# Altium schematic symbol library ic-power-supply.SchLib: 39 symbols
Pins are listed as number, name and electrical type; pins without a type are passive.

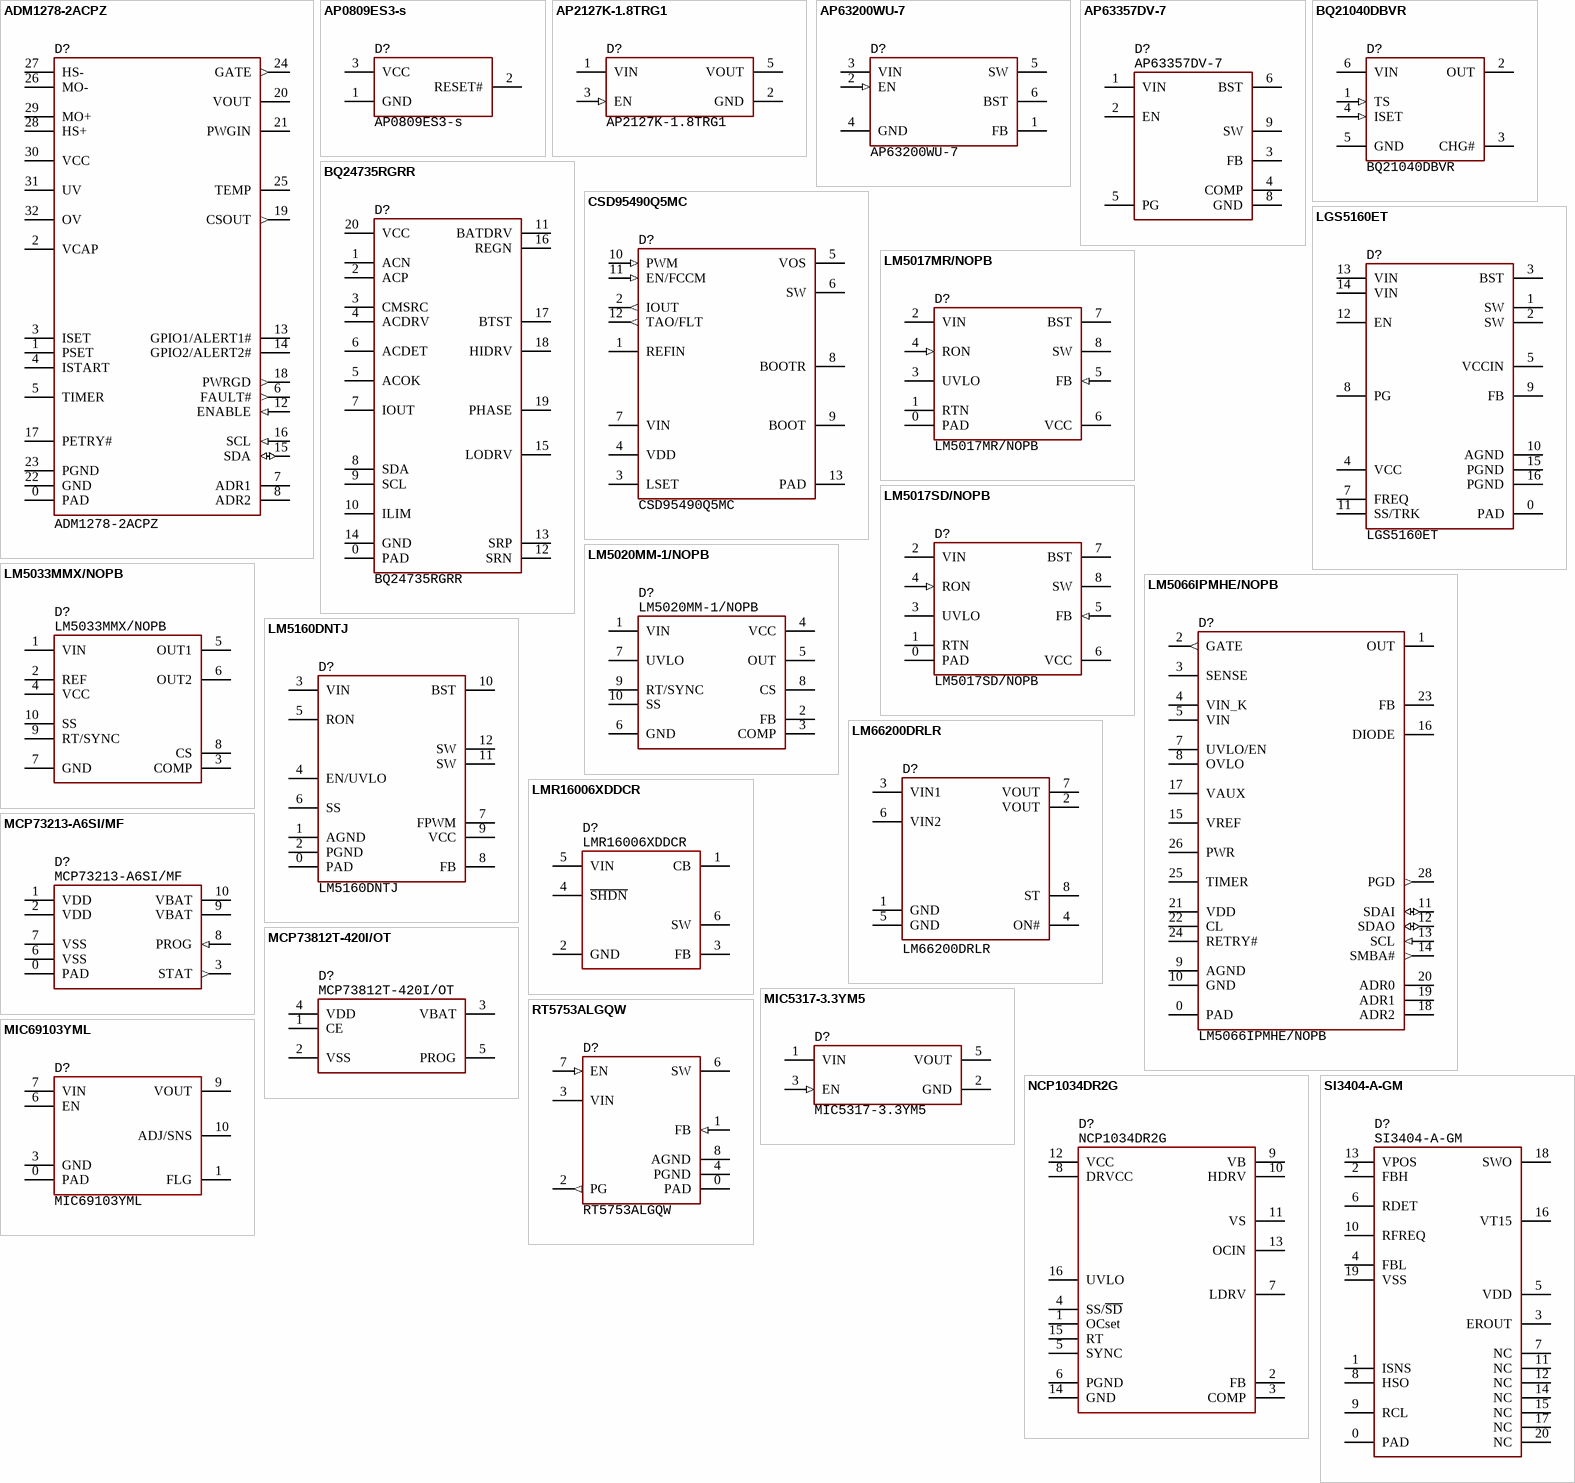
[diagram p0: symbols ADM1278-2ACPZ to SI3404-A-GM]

## ADM1278-2ACPZ
designator D?
Hot Swap Controller, supply 4.5...20V, QFN-32, -40...+85°C; Manufacturer: Analog Devices
footprint 32-QFN (5x5, pitch 0.5) (5x5 mm, pitch 0.5 mm, power pad)
pins: 0 PAD, 1 PSET, 2 VCAP, 3 ISET, 4 ISTART, 5 TIMER, 6 FAULT# (out), 7 ADR1, 8 ADR2, 12 ENABLE (in), 13 GPIO1/ALERT1#, 14 GPIO2/ALERT2#, 15 SDA (io), 16 SCL (in), 17 PETRY#, 18 PWRGD (out), 19 CSOUT (out), 20 VOUT, 21 PWGIN, 22 GND, 23 PGND, 24 GATE (out), 25 TEMP, 26 MO-, 27 HS-, 28 HS+, 29 MO+, 30 VCC, 31 UV, 32 OV

## AP0809ES3-s
designator D?
POR supervisor, 2.97V, SOT-23, -40...+105°C; Manufacturer: Chipown
footprint SOT23
pins: 1 GND, 2 RESET#, 3 VCC

## AP2127K-1.8TRG1
designator D?
LDO, output 1.8V, input 2.5...6V, 300 mA, -40...+85°C; Manufacture: Diodes
footprint SOT23-5 (pitch 0.95 mm)
pins: 1 VIN, 2 GND, 3 EN (in), 5 VOUT

## AP63200WU-7
designator D?  PartNumber: AP63200WU-7
Buck sync, 2A, 500kHz, input 3.8...32V, SOT23-6, -40...+85°C; Manufacturer: Diodes
footprint SOT23-6 (pitch 0.95 mm)
pins: 1 FB, 2 EN (in), 3 VIN, 4 GND, 5 SW, 6 BST

## AP63357DV-7
designator D?  PartNumber: AP63357DV-7
Buck sync, 3.5A, 450kHz, input 3.8...32V, DFN3020, -40...+85°C; Manufacturer: Diodes
footprint IC: AP63357DV-7
pins: 1 VIN, 2 EN, 3 FB, 4 COMP, 5 PG, 6 BST, 8 GND, 9 SW

## BQ21040DBVR
designator D?
Charger 1S, 800 mA, supply 3.5...28V, SOT23-6, 0...+125°C; Manufacture: Texas Instruments
footprint SOT23-6 (pitch 0.95 mm)
pins: 1 TS (in), 2 OUT, 3 CHG#, 4 ISET (in), 5 GND, 6 VIN

## BQ24735RGRR
designator D?
Charger 1...4S, 8A, supply 4.5...24V, QFN-20, -40...+85°C; Manufacture: Texas Instruments
footprint 20-QFN (3.5x3.5) (20-VQFN, pitch 0.5 mm)
pins: 0 PAD, 1 ACN, 2 ACP, 3 CMSRC, 4 ACDRV, 5 ACOK, 6 ACDET, 7 IOUT, 8 SDA, 9 SCL, 10 ILIM, 11 BATDRV, 12 SRN, 13 SRP, 14 GND, 15 LODRV, 16 REGN, 17 BTST, 18 HIDRV, 19 PHASE, 20 VCC

## CSD95490Q5MC
designator D?
DrMOS, input 3...16V, supply 4.75...5.25V, 75A, up to 1.25 MHz, QFN 5x6, -40...+125°C; Manufacturer: Texas Instruments
footprint IC: CSD95490Q5MC
pins: 1 REFIN, 2 IOUT (out), 3 LSET, 4 VDD, 5 VOS, 6 SW, 7 VIN, 8 BOOTR, 9 BOOT, 10 PWM (in), 11 EN/FCCM (in), 12 TAO/FLT (out), 13 PAD

## LGS5160ET
designator D?
Buck sync, 2.5A, up to 2 MHz, supply 4...60V, TSSOP-16, -40...+125°C; Manufacturer: Legend-Si
footprint 16-SSOP (PAD) (pitch 0.635 mm)
pins: 0 PAD, 1 SW, 2 SW, 3 BST, 4 VCC, 5 VCCIN, 7 FREQ, 8 PG, 9 FB, 10 AGND, 11 SS/TRK, 12 EN, 13 VIN, 14 VIN, 15 PGND, 16 PGND

## LM5017MR/NOPB
designator D?
Buck sync, 0.6A, 1MHz, supply 7.5...100V, SOIC-8, -40...+125°C; Manufacturer: Texas Instruments
footprint 8-SOIC-PAD (pitch 1.27 mm, power pad)
pins: 0 PAD, 1 RTN, 2 VIN, 3 UVLO, 4 RON (in), 5 FB (in), 6 VCC, 7 BST, 8 SW

## LM5017SD/NOPB
designator D?
Buck sync, 0.6A, 1MHz, supply 7.5...100V, WSON-8, -40...+125°C; Manufacturer: Texas Instruments
footprint 8-WSON (4x4) (4x4 mm, pitch 0.8 mm, power pad)
pins: 0 PAD, 1 RTN, 2 VIN, 3 UVLO, 4 RON (in), 5 FB (in), 6 VCC, 7 BST, 8 SW

## LM5020MM-1/NOPB
designator D?
PWM controller, 100...1000 kHz, supply 13...100V, MSOP-10, -40...+125°C; Manufacture: Texas Instruments
footprint 10-MSOP (3x3 mm, pitch 0.5 mm)
pins: 1 VIN, 2 FB, 3 COMP, 4 VCC, 5 OUT, 6 GND, 7 UVLO, 8 CS, 9 RT/SYNC, 10 SS

## LM5033MMX/NOPB
designator D?
PWM controller, PP, 100...1000 kHz, supply 15...100V, MSOP-10, -40...+125°C; Manufacture: Texas Instruments
footprint 10-MSOP (3x3 mm, pitch 0.5 mm)
pins: 1 VIN, 2 REF, 3 COMP, 4 VCC, 5 OUT1, 6 OUT2, 7 GND, 8 CS, 9 RT/SYNC, 10 SS

## LM5066IPMHE/NOPB
designator D?
Hot Swap Controller, supply 10...80V, HTSSOP-28, -40...+125°C; Manufacturer: Texas Instruments
footprint 28-TSSOP-PAD (pitch 0.65 mm)
pins: 0 PAD, 1 OUT, 2 GATE (out), 3 SENSE, 4 VIN_K, 5 VIN, 7 UVLO/EN, 8 OVLO, 9 AGND, 10 GND, 11 SDAI (io), 12 SDAO (io), 13 SCL (in), 14 SMBA# (out), 15 VREF, 16 DIODE, 17 VAUX, 18 ADR2, 19 ADR1, 20 ADR0, 21 VDD, 22 CL, 23 FB, 24 RETRY#, 25 TIMER, 26 PWR, 28 PGD (out)

## LM5160DNTJ
designator D?
Buck sync, 2A, up to 1MHz, input 4.5...65V, output 2...60V, WSON-12, -40...+85°C; Manufacturer: Texas Instruments
footprint 12-WSON (4x4x0.5)
pins: 0 PAD, 1 AGND, 2 PGND, 3 VIN, 4 EN/UVLO, 5 RON, 6 SS, 7 FPWM, 8 FB, 9 VCC, 10 BST, 11 SW, 12 SW

## LM66200DRLR
designator D?
Dual OR controller, 2.5A, supply 1.6...5.5V, SOT-5X3, -40...+125°C; Manufacture: Texas Instruments
footprint SOT-583 (pitch 0.95 mm)
pins: 1 GND, 2 VOUT, 3 VIN1, 4 ON#, 5 GND, 6 VIN2, 7 VOUT, 8 ST

## LMR16006XDDCR
designator D?
Buck sync, 0.6A, 700kHz, supply 4...60V, SOT23-6, -40...+125°C; Manufacturer: Texas Instruments
footprint SOT23-6 (pitch 0.95 mm)
pins: 1 CB, 2 GND, 3 FB, 4 ~{SHDN}, 5 VIN, 6 SW

## MCP73213-A6SI/MF
designator D?
Charger 2S, 1.1A, supply 4.2...13V, DFN-10, -40...+85°C; Manufacture: Microchip
footprint 10-DFN (3x3) (3x3 mm, pitch 0.5 mm, power pad)
pins: 0 PAD, 1 VDD, 2 VDD, 3 STAT (out), 6 VSS, 7 VSS, 8 PROG (in), 9 VBAT, 10 VBAT

## MCP73812T-420I/OT
designator D?
Charger 1S, 500 mA, supply 3.75...6V, SOT23-5, -40...+85°C; Manufacture: Microchip
footprint SOT23-5 (pitch 0.95 mm)
pins: 1 CE, 2 VSS, 3 VBAT, 4 VDD, 5 PROG

## MIC5317-3.3YM5
designator D?
LDO, output 3.3V, input 2.5...6V, 150 mA, -40...+85°C; Manufacture: Diodes
footprint SOT23-5 (pitch 0.95 mm)
pins: 1 VIN, 2 GND, 3 EN (in), 5 VOUT

## MIC69103YML
designator D?
LDO, 1A, dropout 0.5V, supply 1.65...5.5V, DFN-8, -40...+125°C; Manufacturer: Microchip
footprint 10-DFN (3x3) (3x3 mm, pitch 0.5 mm, power pad)
pins: 0 PAD, 1 FLG, 3 GND, 6 EN, 7 VIN, 9 VOUT, 10 ADJ/SNS

## NCP1034DR2G
designator D?
Buck controller, 2A, 25...500kHz, supply 10 ...100V, WSON-8, -40...+125°C; Manufacturer: ON Semiconductor
footprint 16-SO (pitch 1.27 mm)
pins: 1 OCset, 2 FB, 3 COMP, 4 SS/~{SD}, 5 SYNC, 6 PGND, 7 LDRV, 8 DRVCC, 9 VB, 10 HDRV, 11 VS, 12 VCC, 13 OCIN, 14 GND, 15 RT, 16 UVLO

## RT5753ALGQW
designator D?
Buck sync, 3A, input 2.5...5.5V, 1.2 MHz, output 0.6V, WDFN-8L, -40...+125°C; Manufacturer: Richtek
footprint 8-DFN (2x2, 0.5 mm)
pins: 0 PAD, 1 FB (in), 2 PG (out), 3 VIN, 4 PGND, 6 SW, 7 EN (in), 8 AGND

## SI3404-A-GM
designator D?
PoE, supply 1.5...57V, 600 mA, 470 kHz, QFN-20, -40...+125°C; Manufacture: Skyworks
footprint 20-QFN (4x4, pitch 0.5) (4x4 mm, pitch 0.5 mm, power pad)
pins: 0 PAD, 1 ISNS, 2 FBH, 3 EROUT, 4 FBL, 5 VDD, 6 RDET, 7 NC, 8 HSO, 9 RCL, 10 RFREQ, 11 NC, 12 NC, 13 VPOS, 14 NC, 15 NC, 16 VT15, 17 NC, 18 SWO, 19 VSS, 20 NC

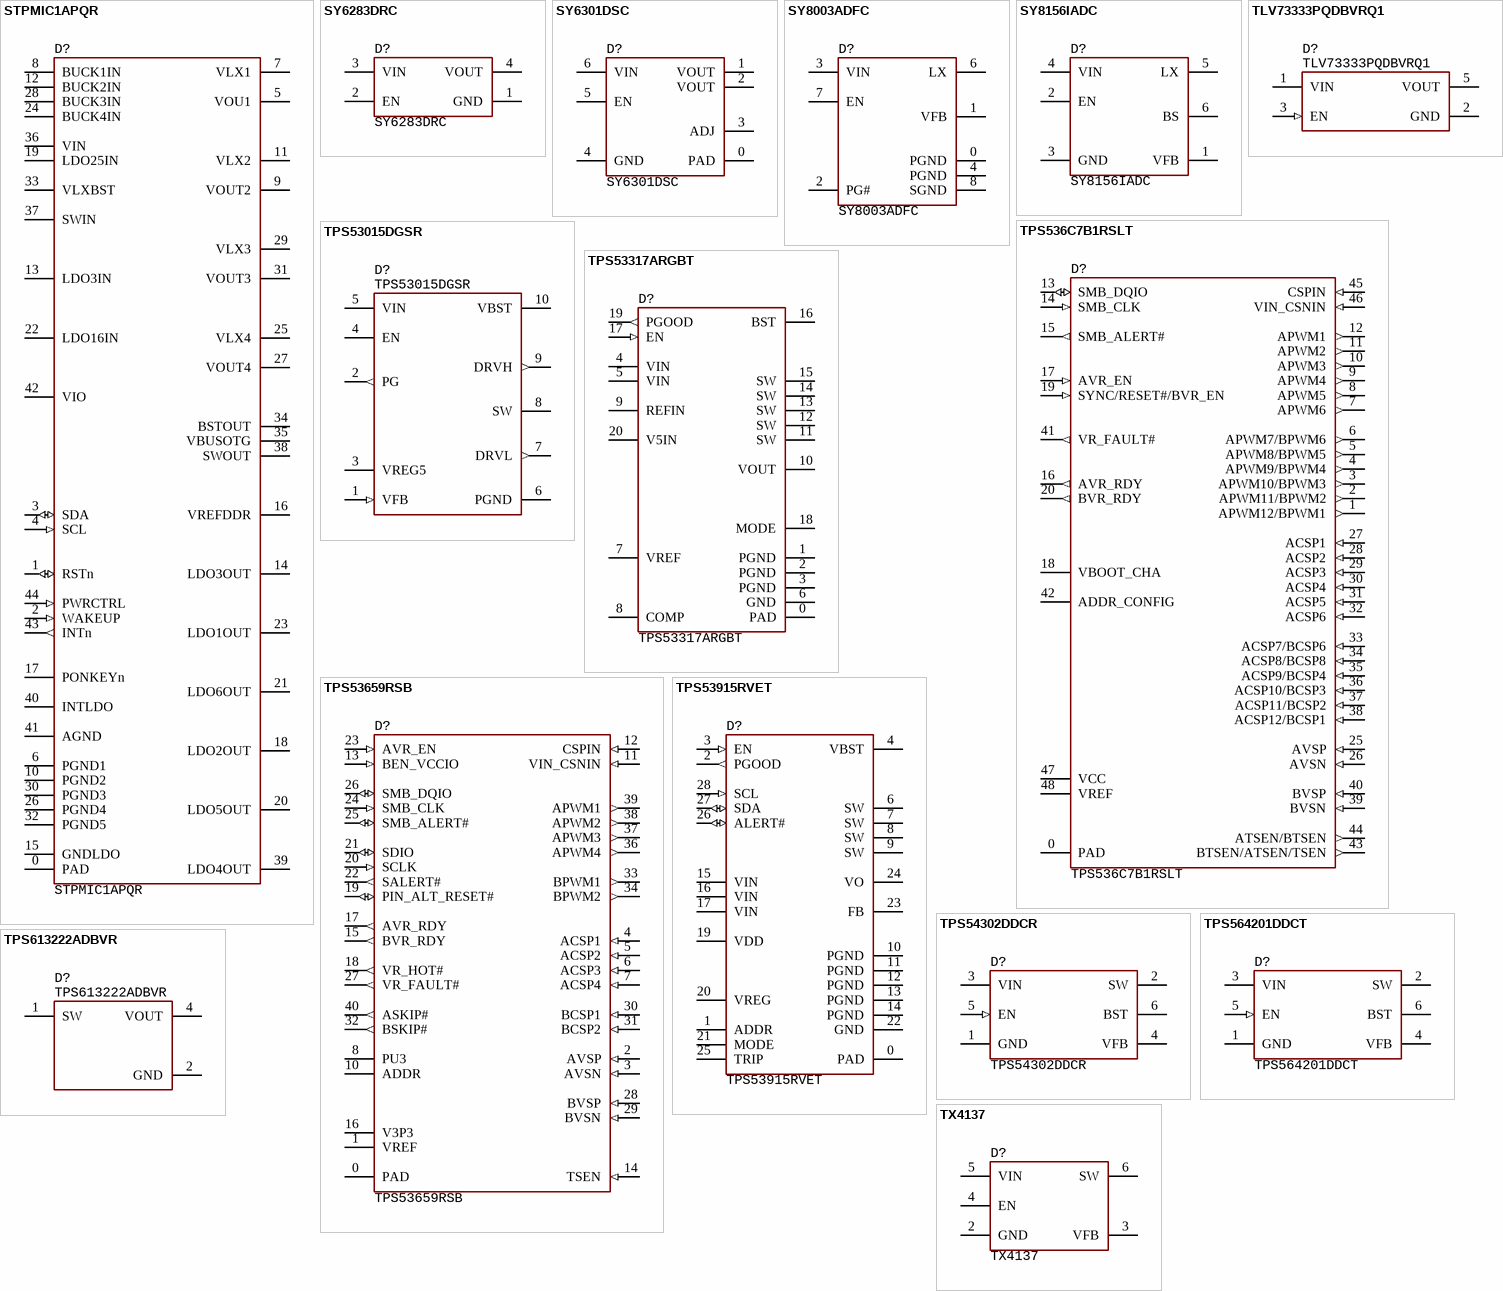
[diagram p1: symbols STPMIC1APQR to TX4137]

## STPMIC1APQR
designator D?  PartNumber: STPMIC1APQR
PMIC, 4 DC/DC + 7 LDO, input 2.8...5.5V, 44-WFQFN, -40...+105°C; Manufacturer: STMicroelectronics
footprint 44-WFQFN (5x6, pitch 0.4) (44-QFN, 5x6mm, pitch 0,40mm)
pins: 0 PAD, 1 RSTn (io), 2 WAKEUP (in), 3 SDA (io), 4 SCL (in), 5 VOU1, 6 PGND1, 7 VLX1, 8 BUCK1IN, 9 VOUT2, 10 PGND2, 11 VLX2, 12 BUCK2IN, 13 LDO3IN, 14 LDO3OUT, 15 GNDLDO, 16 VREFDDR, 17 PONKEYn, 18 LDO2OUT, 19 LDO25IN, 20 LDO5OUT, 21 LDO6OUT, 22 LDO16IN, 23 LDO1OUT, 24 BUCK4IN, 25 VLX4, 26 PGND4, 27 VOUT4, 28 BUCK3IN, 29 VLX3, 30 PGND3, 31 VOUT3, 32 PGND5, 33 VLXBST, 34 BSTOUT, 35 VBUSOTG, 36 VIN, 37 SWIN, 38 SWOUT, 39 LDO4OUT, 40 INTLDO, 41 AGND, 42 VIO, 43 INTn (out), 44 PWRCTRL (in)

## SY6283DRC
designator D?
Switches, 2.5...5.5V, 3A, DFN-4, -40...+85°C; Manufacturer: Silergy
footprint 4-DFN (1.2x1.6, 0.5 mm)
pins: 1 GND, 2 EN, 3 VIN, 4 VOUT

## SY6301DSC
designator D?
LDO, 1A, dropout 0.18V, supply 1.6...5.5V, DFN-6, -40...+125°C; Manufacturer: Silergy
footprint 6-DFN (3x3, 0.95 mm)
pins: 0 PAD, 1 VOUT, 2 VOUT, 3 ADJ, 4 GND, 5 EN, 6 VIN

## SY8003ADFC
designator D?
Buck sync, 3A, 1MHz, input 2.7...5.5V, DFN-8, -40...+85°C; Manufacturer: Silergy
footprint 8-DFN (2x2, 0.5 mm)
pins: 0 PGND, 1 VFB, 2 PG#, 3 VIN, 4 PGND, 6 LX, 7 EN, 8 SGND

## SY8156IADC
designator D?
Buck sync, 6A, 400kHz, input 4.5...18V, SOT23-6, -40...+85°C; Manufacturer: Silergy
footprint SOT23-6 (pitch 0.95 mm)
pins: 1 VFB, 2 EN, 3 GND, 4 VIN, 5 LX, 6 BS

## TLV73333PQDBVRQ1
designator D?
LDO, output 3.3V, input 1.4...5.5V, 300 mA, -40...+85°C; Manufacturer: Texas Instruments
footprint SOT23-5 (pitch 0.95 mm)
pins: 1 VIN, 2 GND, 3 EN (in), 5 VOUT

## TPS536C7B1RSLT
designator D?
12 phase PMIC, supply 2.97...3.6V, 0.3...2MHz, QFN-48, -40...+125°C; Manufacturer: Texas Instruments
footprint 48-QFN (6x6, pitch 0.4) (6x6 mm, pitch 0.4 mm, power pad)
pins: 0 PAD, 1 APWM12/BPWM1 (out), 2 APWM11/BPWM2 (out), 3 APWM10/BPWM3 (out), 4 APWM9/BPWM4 (out), 5 APWM8/BPWM5 (out), 6 APWM7/BPWM6 (out), 7 APWM6 (out), 8 APWM5 (out), 9 APWM4 (out), 10 APWM3 (out), 11 APWM2 (out), 12 APWM1 (out), 13 SMB_DQIO (io), 14 SMB_CLK (in), 15 SMB_ALERT# (out), 16 AVR_RDY (out), 17 AVR_EN (in), 18 VBOOT_CHA, 19 SYNC/RESET#/BVR_EN (in), 20 BVR_RDY (out), 25 AVSP (in), 26 AVSN (in), 27 ACSP1 (in), 28 ACSP2 (in), 29 ACSP3 (in), 30 ACSP4 (in), 31 ACSP5 (in), 32 ACSP6 (in), 33 ACSP7/BCSP6 (in), 34 ACSP8/BCSP8 (in), 35 ACSP9/BCSP4 (in), 36 ACSP10/BCSP3 (in), 37 ACSP11/BCSP2 (in), 38 ACSP12/BCSP1 (in), 39 BVSN (in), 40 BVSP (in), 41 VR_FAULT# (out), 42 ADDR_CONFIG, 43 BTSEN/ATSEN/TSEN (out), 44 ATSEN/BTSEN (out), 45 CSPIN (in), 46 VIN_CSNIN (in), 47 VCC, 48 VREF

## TPS53015DGSR
designator D?
Buck controller, 25A, 500 kHz, supply 4.5...28V, MSOP-10, -40...+125°C; Manufacture: Texas Instruments
footprint 10-MSOP (3x3 mm, pitch 0.5 mm)
pins: 1 VFB (in), 2 PG (out), 3 VREG5, 4 EN, 5 VIN, 6 PGND, 7 DRVL (out), 8 SW, 9 DRVH (out), 10 VBST

## TPS53317ARGBT
designator D?
DDR VTT buck, 6A, 600...1000kHz, supply 0.9...6V, output 0.45...2V, VQFN-20, -40...+125°C; Manufacturer: Texas Instruments
footprint 20-QFN (4x3.5, pitch 0.5) (20-VQFN, pitch 0.5 mm)
pins: 0 PAD, 1 PGND, 2 PGND, 3 PGND, 4 VIN, 5 VIN, 6 GND, 7 VREF, 8 COMP, 9 REFIN, 10 VOUT, 11 SW, 12 SW, 13 SW, 14 SW, 15 SW, 16 BST, 17 EN (in), 18 MODE, 19 PGOOD (out), 20 V5IN

## TPS53659RSB
designator D?
6 phase PMIC, supply 2.97...3.5V, 0.3...1MHz, QFN-40, -40...+125°C; Manufacturer: Texas Instruments; Manufacturer Part Number: TPS53659RSBT
footprint 40-QFN (5x5) (5x mm, pitch 0.4 mm, power pad)
pins: 0 PAD, 1 VREF, 2 AVSP (in), 3 AVSN (in), 4 ACSP1 (in), 5 ACSP2 (in), 6 ACSP3 (in), 7 ACSP4 (in), 8 PU3, 10 ADDR, 11 VIN_CSNIN (in), 12 CSPIN (in), 13 BEN_VCCIO (in), 14 TSEN (in), 15 BVR_RDY (out), 16 V3P3, 17 AVR_RDY (out), 18 VR_HOT# (out), 19 PIN_ALT_RESET# (io), 20 SCLK (in), 21 SDIO (io), 22 SALERT# (out), 23 AVR_EN (in), 24 SMB_CLK (in), 25 SMB_ALERT# (io), 26 SMB_DQIO (io), 27 VR_FAULT# (out), 28 BVSP (in), 29 BVSN (in), 30 BCSP1 (in), 31 BCSP2 (in), 32 BSKIP# (out), 33 BPWM1 (out), 34 BPWM2 (out), 36 APWM4 (out), 37 APWM3 (out), 38 APWM2 (out), 39 APWM1 (out), 40 ASKIP# (out)

## TPS53915RVET
designator D?
Buck sync, 12A, 1000 kHz, supply 1.5...18V, output 0.6...5.5V, VQFN-28, -40...+85°C; Manufacturer: Texas Instruments
footprint 28-QFN (4.5x3.5, pitch 0.4) (pitch 0.95 mm)
pins: 0 PAD, 1 ADDR, 2 PGOOD (out), 3 EN (in), 4 VBST, 6 SW, 7 SW, 8 SW, 9 SW, 10 PGND, 11 PGND, 12 PGND, 13 PGND, 14 PGND, 15 VIN, 16 VIN, 17 VIN, 19 VDD, 20 VREG, 21 MODE, 22 GND, 23 FB, 24 VO, 25 TRIP, 26 ALERT# (io), 27 SDA (io), 28 SCL (in)

## TPS54302DDCR
designator D?
Buck sync, 3A, 400kHz, supply 4.5...28V, SOT-23-6, -40...+85°C; Manufacturer: Texas Instruments
footprint SOT23-6 (pitch 0.95 mm)
pins: 1 GND, 2 SW, 3 VIN, 4 VFB, 5 EN (in), 6 BST

## TPS564201DDCT
designator D?
Buck sync, 4A, 560kHz, supply 4.5...17V, SOT-23-6, -40...+85°C; Manufacturer: Texas Instruments
footprint SOT23-6 (pitch 0.95 mm)
pins: 1 GND, 2 SW, 3 VIN, 4 VFB, 5 EN (in), 6 BST

## TPS613222ADBVR
designator D?
Boost, 1.8A, input 0.9...5.5V, output 1.8...5.5V, SOT23-5, 40...+85°C; Manufacture: Texas Instruments
footprint SOT23-5 (pitch 0.95 mm)
pins: 1 SW, 2 GND, 4 VOUT

## TX4137
designator D?
Buck sync, 0.6A, 1MHz, input 5.5...60V, SOT23-6, -40...+85°C; Manufacturer: XDS
footprint SOT23-6 (pitch 0.95 mm)
pins: 2 GND, 3 VFB, 4 EN, 5 VIN, 6 SW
